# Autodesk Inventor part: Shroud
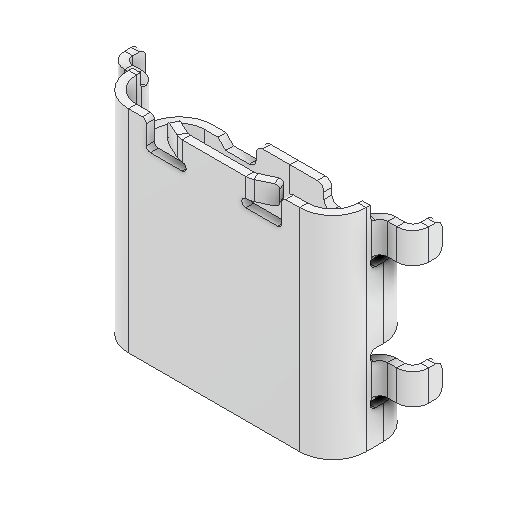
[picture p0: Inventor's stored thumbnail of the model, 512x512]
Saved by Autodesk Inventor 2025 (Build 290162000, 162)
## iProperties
Created: 2025-05
Part Number: Shroud
Material: Aluminium 6061
Document SubType Name: Modeling
Designer: R5800u
Density: 2.7 g/cm^3
Appearance: Default
Author: R5800u
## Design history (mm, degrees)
feature "Corps1"
node "Solido1"
